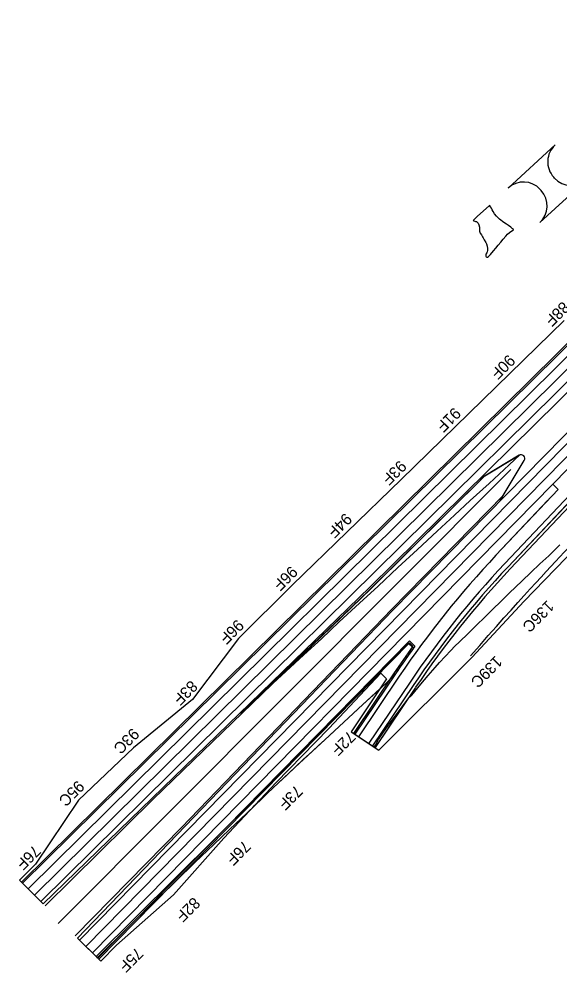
# Model space of a CAD drawing. Extents: x 2163396 to 2173129, y 605545 to 614595.
# Drawn here: x 2163396 to 2164110, y 605545 to 606803 of the extents above; entities that cross this region are included whole.
import ezdxf

# ---------------------------------------------------------------- set-up
doc = ezdxf.new("R2010")
doc.units = 0
for name, color, linetype in [('RD_PD_AsphRem', 7, 'Continuous'), ('RD_PD_CstnLmt', 7, 'Continuous'), ('RD_PD_DR_Ditch', 7, 'Continuous'), ('RD_PD_EarthShd', 7, 'Continuous'), ('RD_PD_Final_LnLine', 7, 'Continuous'), ('RD_PD_Final_TrvlWay', 7, 'Continuous'), ('RD_PD_GR', 7, 'Continuous'), ('RD_PD_TX_CstnLmt', 7, 'Continuous')]:
    doc.layers.add(name, color=color, linetype=linetype)

msp = doc.modelspace()

# ---------------------------------------------------------------- linework, layer by layer
at = {"layer": 'RD_PD_AsphRem'}
for p, q in [((2164359.8, 606418.6), (2164041.5, 606080.9)), ((2164055.9, 606227.8), (2164010.4, 606200.5)), ((2164010.4, 606200.5), (2163857.2, 606049.3)), ((2163857.2, 606049.3), (2163688.5, 605887.3)), ((2163909.4, 605980.5), (2163707.9, 605775.1)), ((2163916.5, 605973.5), (2163909.4, 605980.5)), ((2163891.7, 605937.8), (2163893, 605939.8)), ((2163916.2, 605924.2), (2163862.7, 605844.7)), ((2163707.9, 605775.1), (2163498.1, 605566.9)), ((2163498.1, 605566.9), (2163499.6, 605565.4))]:
    msp.add_line(p, q, dxfattribs=at)
for points in [[(2163995.2, 606537.4), (2163998.4, 606536.2), (2163999.6, 606536), (2164000.9, 606535.2), (2164001.8, 606533.7), (2164002.7, 606531.8), (2164003.7, 606528.7), (2164003.6, 606526.2), (2164003.8, 606523.5), (2164004.8, 606520.8), (2164006.2, 606518.4), (2164007.7, 606515.9), (2164008.5, 606514.4), (2164009.8, 606512.1), (2164012.1, 606508.5), (2164012.9, 606506.5), (2164013.7, 606503.4), (2164014.5, 606500.4), (2164014.4, 606497.9), (2164013.9, 606496.2), (2164013.3, 606494.7), (2164012.3, 606492.9), (2164012, 606491.4), (2164012.1, 606490.2), (2164012.7, 606489.6), (2164013.3, 606489.2), (2164013.6, 606489.2), (2164014.3, 606489.1), (2164015.7, 606490), (2164018.2, 606492.6), (2164022.3, 606497.2), (2164025.4, 606500.9), (2164028.5, 606504.7), (2164031.9, 606508.9), (2164035.1, 606512.8), (2164038.4, 606516.7), (2164040.7, 606519.3), (2164043.5, 606521.8), (2164045.3, 606523), (2164047.2, 606524.2), (2164048.4, 606525), (2164048.5, 606525.7), (2164047.5, 606526.6), (2164045.4, 606528.1), (2164045.1, 606528.4), (2164042, 606530.6), (2164039.5, 606532.5), (2164035.7, 606534.7), (2164030.1, 606539.3), (2164026.1, 606543), (2164023.7, 606546.1), (2164021.9, 606549.1), (2164020.3, 606551.6), (2164019.4, 606553.5), (2164018.3, 606555.3), (2164017.1, 606557.5)], [(2164017.1, 606557.5), (2164016.9, 606557.4), (2164000.9, 606542.7), (2163995.2, 606537.4)], [(2163688.5, 605887.3), (2163702.1, 605900), (2163725.5, 605921.8), (2163748.1, 605942.7), (2163772.1, 605964.7), (2163795.2, 605986), (2163818.8, 606008.1), (2163845.6, 606032.8), (2163870, 606055.5), (2163896.2, 606079.9), (2163921.9, 606103.5), (2163948.1, 606127.8), (2163965, 606143.5), (2163970.9, 606149), (2163991.6, 606168.1), (2164016.4, 606190.8), (2164043, 606215.4), (2164056.9, 606228.3)], [(2163862.7, 605844.7), (2163865.3, 605843.5), (2163866.4, 605845.7), (2163870.6, 605853.1), (2163875.2, 605860.2), (2163880.1, 605867.2), (2163892.7, 605884), (2163901.8, 605896), (2163906.4, 605902.6), (2163911.8, 605909.8), (2163912.7, 605909.7), (2163914.3, 605911.5), (2163926.5, 605926), (2163935.9, 605937.3), (2163945.1, 605947.9), (2163951.2, 605954.8), (2163958.5, 605962.7), (2163966.1, 605970.6), (2163971.3, 605976), (2163977.2, 605981.9), (2163988.7, 605993.1), (2163998.3, 606002.7), (2164012, 606015.9), (2164021.3, 606025), (2164031.7, 606035.1), (2164043.1, 606046), (2164060, 606062.3), (2164071.6, 606073.3), (2164083.5, 606084.6), (2164095.1, 606095.5), (2164109.9, 606109.9)], [(2163499.6, 605565.4), (2163502, 605567.9), (2163511.9, 605577.7), (2163527.5, 605593.1), (2163545.9, 605611.2), (2163564.2, 605628.8), (2163583, 605646.7), (2163603.1, 605666.5), (2163628.3, 605691), (2163653.4, 605714.9), (2163674.1, 605734.5), (2163696.8, 605756.1), (2163717.7, 605775.9), (2163724.2, 605782.3), (2163738.7, 605796.1), (2163760.2, 605816.3), (2163783.4, 605837.8), (2163799.8, 605852.9), (2163824.9, 605876.1), (2163849.8, 605899.1), (2163872.6, 605920), (2163891.7, 605937.8)], [(2163498.1, 605566.9), (2163498.1, 605566.9), (2163498.1, 605566.9)]]:
    msp.add_lwpolyline(points, dxfattribs=at)
for centre, radius, start, end in [((2164058.5, 606223.6), 5, 108.7075, 121.0267), ((2164936.8, 605237.1), 1230.3, 136.6938, 146.0495), ((2164936.8, 605237.1), 1258.3, 144.1784, 146.0495)]:
    msp.add_arc(centre, radius, start, end, dxfattribs=at)
at = {"layer": 'RD_PD_CstnLmt'}
for p, q in [((2164115.4, 606405.5), (2164043.9, 606335.6)), ((2164043.9, 606335.6), (2163972.2, 606265.8)), ((2163972.2, 606265.8), (2163900.5, 606196.1)), ((2163900.5, 606196.1), (2163828.7, 606126.5)), ((2163828.7, 606126.5), (2163756.9, 606056.9)), ((2164131.7, 606106.8), (2164062.1, 606034.9)), ((2163756.9, 606056.9), (2163686, 605986.4)), ((2164062.1, 606034.9), (2163993.9, 605961.7)), ((2163686, 605986.4), (2163625.1, 605905.9)), ((2163993.9, 605961.7), (2163871.1, 605839.2)), ((2163873.6, 605940.5), (2163805.1, 605867.6)), ((2163881.2, 605933), (2163834.3, 605863.3)), ((2163881.2, 605933), (2163873.6, 605940.5)), ((2163625.1, 605905.9), (2163547.2, 605842.3)), ((2163805.1, 605867.6), (2163735.3, 605796)), ((2163834.3, 605863.3), (2163871.1, 605839.2)), ((2163547.2, 605842.3), (2163474.9, 605773.2)), ((2163735.3, 605796), (2163666.7, 605723.1)), ((2163474.9, 605773.2), (2163417.9, 605688.8)), ((2163666.7, 605723.1), (2163600.2, 605648.3)), ((2163418, 605688.8), (2163397, 605667.5)), ((2163397, 605667.5), (2163428, 605636.6)), ((2163600.2, 605648.3), (2163525.1, 605582)), ((2163504.3, 605560.8), (2163473.3, 605591.4)), ((2163525.1, 605582), (2163504.3, 605560.8))]:
    msp.add_line(p, q, dxfattribs=at)
msp.add_lwpolyline([(2163872.3, 605919.8), (2163849.8, 605899.1), (2163837.3, 605887.6), (2163824.9, 605876.1), (2163812.3, 605864.5), (2163799.8, 605852.9), (2163791.6, 605845.3), (2163783.4, 605837.8), (2163771.8, 605827), (2163749.5, 605806.2), (2163738.7, 605796.1), (2163731.5, 605789.2), (2163724.2, 605782.3), (2163721, 605779.1), (2163717.7, 605775.9), (2163707.3, 605766), (2163705.8, 605764.6)], dxfattribs=at)
at = {"layer": 'RD_PD_DR_Ditch'}
msp.add_open_spline([(2163992.1, 605963.5), (2164058.1, 606039), (2164126.3, 606112.1), (2164196.5, 606183.4), (2164268.9, 606252.4), (2164363.9, 606298.9), (2163992.1, 605963.5), (2164363.9, 606298.9)], degree=3, dxfattribs=at)
at = {"layer": 'RD_PD_EarthShd'}
for p, q in [((2164044.4, 606078.2), (2164654.4, 606725.4)), ((2164394.9, 606647), (2163399.7, 605664.9)), ((2164011.3, 606201), (2163860.7, 606052.4)), ((2164035.5, 606175.4), (2163888, 606025.1)), ((2163860.7, 606052.4), (2163573.2, 605774.3)), ((2163888, 606025.1), (2163610.6, 605736.9)), ((2163911.4, 605980.5), (2163501.8, 605563.3)), ((2163915.9, 605976.1), (2163911.4, 605980.5)), ((2163891.3, 605940.9), (2163837.6, 605861.2)), ((2163919.5, 605921.9), (2163866.1, 605842.5)), ((2163573.2, 605774.3), (2163430.8, 605633.7)), ((2163610.6, 605736.9), (2163470.4, 605594.2))]:
    msp.add_line(p, q, dxfattribs=at)
for radius, start in [(1226.3, 136.6938), (1260.3, 144.0975)]:
    msp.add_arc((2164936.8, 605237.1), radius, start, 146.0495, dxfattribs=at)
at = {"layer": 'RD_PD_Final_LnLine'}
for p, q in [((2164570, 606803), (2163408.2, 605656.4)), ((2164578.5, 606794.4), (2163416.7, 605647.9)), ((2164586.9, 606785.9), (2163425.2, 605639.4)), ((2164619.7, 606753.2), (2163476.1, 605588.6)), ((2164628.3, 606744.8), (2163484.6, 605580.1)), ((2164636.8, 606736.3), (2164100.3, 606189.9)), ((2164037.1, 606085), (2164644.1, 606729)), ((2164004, 606196.6), (2164055.9, 606227.8)), ((2164031.1, 606168.1), (2164062.8, 606221)), ((2164100.3, 606189.9), (2163493.2, 605571.7)), ((2164025.5, 606096), (2164107.4, 606182.9)), ((2164107.4, 606182.9), (2164100.3, 606189.9)), ((2164025.5, 606096), (2164094.1, 606168.8)), ((2163898, 605936.5), (2163844.3, 605856.7)), ((2163911.3, 605927.5), (2163857.8, 605848.1))]:
    msp.add_line(p, q, dxfattribs=at)
for centre, radius, start, end in [((2164058.5, 606223.6), 5, 329.0992, 121.0267), ((2164936.8, 605237.1), 1252.3, 136.6938, 146.0495), ((2164936.8, 605237.1), 1236.3, 136.6938, 146.0495)]:
    msp.add_arc(centre, radius, start, end, dxfattribs=at)
at = {"layer": 'RD_PD_Final_TrvlWay'}
for p, q in [((2164594.1, 606778.9), (2163859.3, 606053.8)), ((2164612.7, 606760.3), (2163889.4, 606023.7)), ((2164041.5, 606080.9), (2164648.3, 606724.8)), ((2164396.3, 606645.5), (2163401.1, 605663.5)), ((2164103.4, 606637), (2164041.4, 606580.2)), ((2164145.1, 606591.4), (2164083.4, 606534.6)), ((2164102.8, 606593.2), (2164101.6, 606594.4)), ((2164085.1, 606577), (2164083.7, 606578.5)), ((2163859.3, 606053.8), (2163428, 605636.6)), ((2163889.4, 606023.7), (2163473.3, 605591.4)), ((2163911.4, 605983.3), (2163500.3, 605564.7)), ((2163918.6, 605976.3), (2163911.4, 605983.3)), ((2163893, 605939.8), (2163839.3, 605860)), ((2163916.2, 605924.2), (2163862.7, 605844.7)), ((2163839.3, 605860), (2163862.7, 605844.7)), ((2163401.1, 605663.5), (2163428, 605636.6)), ((2163500.3, 605564.7), (2163473.3, 605591.4))]:
    msp.add_line(p, q, dxfattribs=at)
for centre, radius, start, end in [((2164123.7, 606614.8), 30, 132.3748, 222.7195), ((2164061.7, 606558.1), 30, 42.7195, 132.5874), ((2164124.8, 606613.5), 30, 222.7195, 312.4957), ((2164063, 606556.6), 30, 312.7391, 42.7195), ((2164936.8, 605237.1), 1230.3, 136.6938, 146.0495), ((2164936.8, 605237.1), 1258.3, 144.0192, 146.0495)]:
    msp.add_arc(centre, radius, start, end, dxfattribs=at)
at = {"layer": 'RD_PD_GR'}
msp.add_line((2164044.9, 606208.9), (2163447.9, 605610.5), dxfattribs=at)

# ---------------------------------------------------------------- texts
at = {"layer": 'RD_PD_TX_CstnLmt'}
for s, p in [('88F', (2164113.3, 606431.6)), ('90F', (2164041.8, 606361.7)), ('91F', (2163970.1, 606292)), ('93F', (2163898.4, 606222.3)), ('94F', (2163826.5, 606152.7)), ('96F', (2163754.8, 606083)), ('136C', (2164093.1, 606037.6)), ('96F', (2163683.9, 606012.5)), ('139C', (2164024.9, 605964.5)), ('83F', (2163622.9, 605932.1)), ('93C', (2163545.9, 605869.3)), ('72F', (2163831.2, 605865.5)), ('95C', (2163473.5, 605800.2)), ('73F', (2163761.5, 605793.9)), ('76F', (2163692.9, 605721)), ('76F', (2163415.8, 605715)), ('82F', (2163626.3, 605646.2)), ('75F', (2163551.2, 605579.9))]:
    msp.add_text(s, height=15, rotation=225.0711, dxfattribs=at).set_placement(p)

doc.saveas('drawing.dxf')
